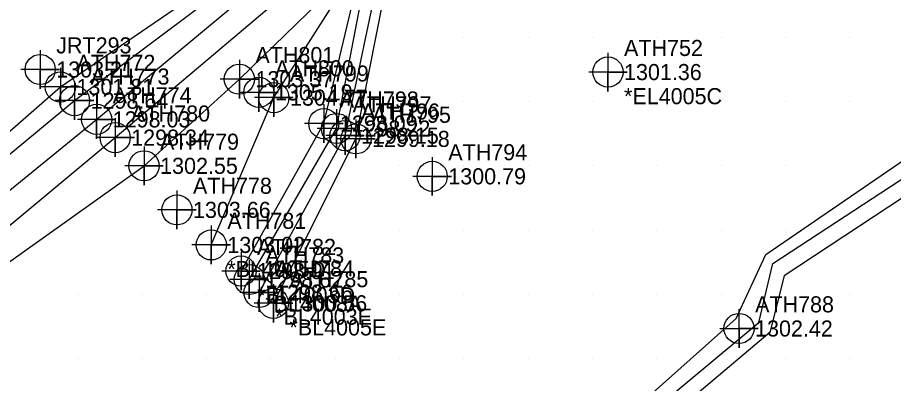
# Model space of a CAD drawing. Extents: x 1234484 to 1235382, y 695050 to 695510.
# Drawn here: x 1234800.6 to 1234936.8, y 695206.2 to 695263.1 of the extents above; entities that cross this region are included whole.
import ezdxf

# ---------------------------------------------------------------- set-up
doc = ezdxf.new("R2010")
doc.units = 0
for name, color, linetype in [('Exist DTM Breakline', 7, 'Continuous'), ('Exist DTM Breakline Cogo Comment', 7, 'Continuous'), ('Exist DTM Breakline Cogo Elevation', 7, 'Continuous'), ('Exist DTM Breakline Cogo Number', 7, 'Continuous'), ('Exist DTM Breakline Cogo Point CELL', 7, 'Continuous'), ('Exist DTM Breakline Underwater', 7, 'Continuous'), ('Exist DTM Drainline Cogo Comment', 7, 'Continuous'), ('Exist DTM Drainline Cogo Elevation', 7, 'Continuous'), ('Exist DTM Drainline Cogo Number', 7, 'Continuous'), ('Exist DTM Drainline Cogo Point CELL', 7, 'Continuous'), ('Exist DTM QL2 LIDAR Elevation Point', 7, 'Continuous'), ('Exist DTM Regular Point CELL', 7, 'Continuous'), ('Exist DTM Regular Point Cogo Elevation', 7, 'Continuous'), ('Exist DTM Regular Point Cogo Number', 7, 'Continuous'), ('Exist DTM Regular Point Underwater CELL', 7, 'Continuous'), ('Exist DTM Regular Point Underwater Cogo Comment', 7, 'Continuous'), ('Exist DTM Regular Point Underwater Cogo Elevation', 7, 'Continuous'), ('Exist DTM Regular Point Underwater Cogo Number', 7, 'Continuous'), ('Exist Hydro Stream or Body of Water', 7, 'Continuous'), ('Exist Hydro Stream or Body of Water Cogo Elevation', 7, 'Continuous'), ('Exist Hydro Stream or Body of Water Cogo Number', 7, 'Continuous'), ('Exist Hydro Stream or Body of Water Cogo Point CELL', 7, 'Continuous'), ('Old_Level_50', 7, 'Continuous')]:
    doc.layers.add(name, color=color, linetype=linetype)

msp = doc.modelspace()

# ---------------------------------------------------------------- linework, layer by layer
at = {"layer": 'Exist DTM Breakline'}
for points in [[(1234766.2, 695216.412), (1234807.252, 695252.276), (1234839.673, 695274.467), (1234869.326, 695284.86), (1234890.801, 695299.09), (1234911.196, 695302.79), (1234918.594, 695307.818)], [(1234933.683, 695295.436), (1234929.419, 695292.356), (1234942.895, 695281.98), (1234955.338, 695274.07), (1234960.662, 695260.925), (1234955.311, 695244.507), (1234951.042, 695246.761), (1234943.062, 695238.239), (1234919.786, 695222.886), (1234917.573, 695214.076), (1234899.933, 695199.243), (1234885.657, 695179.089)], [(1234882.128, 695182.331), (1234896.107, 695201.799), (1234912.336, 695216.249), (1234916.953, 695226.235), (1234940.483, 695242.348), (1234951.207, 695257.798), (1234946.446, 695265.278), (1234936.421, 695274.091), (1234919.314, 695287.826), (1234914.388, 695289.733)], [(1234840.371, 695218.638), (1234853.212, 695244.202), (1234858.487, 695270.963), (1234871.461, 695273.745), (1234897.697, 695279.312), (1234915.088, 695274.445), (1234918.81, 695282.981)], [(1234773.364, 695206.653), (1234820.257, 695240.015), (1234835.082, 695253.487), (1234852.804, 695270.766)], [(1234830.712, 695227.716), (1234840.448, 695250.618), (1234853.055, 695270.415)]]:
    msp.add_lwpolyline(points, dxfattribs=at)
at = {"layer": 'Exist DTM Breakline Cogo Point CELL'}
for points in [[(1234835.082, 695256.487), (1234835.082, 695250.487), (1234835.082, 695253.487), (1234838.082, 695253.487), (1234832.082, 695253.487)], [(1234807.252, 695255.276), (1234807.252, 695249.276), (1234807.252, 695252.276), (1234810.252, 695252.276), (1234804.252, 695252.276)], [(1234840.448, 695253.618), (1234840.448, 695247.618), (1234840.448, 695250.618), (1234843.448, 695250.618), (1234837.448, 695250.618)], [(1234853.212, 695247.202), (1234853.212, 695241.202), (1234853.212, 695244.202), (1234856.212, 695244.202), (1234850.212, 695244.202)], [(1234820.257, 695243.015), (1234820.257, 695237.015), (1234820.257, 695240.015), (1234823.257, 695240.015), (1234817.257, 695240.015)], [(1234830.712, 695230.716), (1234830.712, 695224.716), (1234830.712, 695227.716), (1234833.712, 695227.716), (1234827.712, 695227.716)], [(1234840.371, 695221.638), (1234840.371, 695215.638), (1234840.371, 695218.638), (1234843.371, 695218.638), (1234837.371, 695218.638)]]:
    msp.add_lwpolyline(points, dxfattribs=at)
for centre in [(1234835.082, 695253.487), (1234807.252, 695252.276), (1234840.448, 695250.618), (1234853.212, 695244.202), (1234820.257, 695240.015), (1234830.712, 695227.716), (1234840.371, 695218.638)]:
    msp.add_circle(centre, 2.344, dxfattribs=at)
at = {"layer": 'Exist DTM Breakline Underwater'}
msp.add_lwpolyline([(1234766.421, 695209.389), (1234812.885, 695247.237), (1234843.411, 695272.621), (1234869.986, 695279.055), (1234895.378, 695289.036), (1234916.238, 695295.408), (1234934.131, 695306.081), (1234961.466, 695329.617), (1234991.436, 695342.664), (1235009.265, 695346.147), (1235040.352, 695365.623), (1235072.367, 695380.008), (1235092.174, 695396.335)], dxfattribs=at)
at = {"layer": 'Exist DTM Drainline Cogo Point CELL'}
for points in [[(1234809.451, 695253.146), (1234809.451, 695247.146), (1234809.451, 695250.146), (1234812.451, 695250.146), (1234806.451, 695250.146)], [(1234848.212, 695249.579), (1234848.212, 695243.579), (1234848.212, 695246.579), (1234851.212, 695246.579), (1234845.212, 695246.579)], [(1234815.763, 695247.4), (1234815.763, 695241.4), (1234815.763, 695244.4), (1234818.763, 695244.4), (1234812.763, 695244.4)], [(1234851.51, 695247.706), (1234851.51, 695241.706), (1234851.51, 695244.706), (1234854.51, 695244.706), (1234848.51, 695244.706)], [(1234835.336, 695226.655), (1234835.336, 695220.655), (1234835.336, 695223.655), (1234838.336, 695223.655), (1234832.336, 695223.655)], [(1234838.142, 695223.308), (1234838.142, 695217.308), (1234838.142, 695220.308), (1234841.142, 695220.308), (1234835.142, 695220.308)]]:
    msp.add_lwpolyline(points, dxfattribs=at)
for centre in [(1234809.451, 695250.146), (1234848.212, 695246.579), (1234815.763, 695244.4), (1234851.51, 695244.706), (1234835.336, 695223.655), (1234838.142, 695220.308)]:
    msp.add_circle(centre, 2.344, dxfattribs=at)
at = {"layer": 'Exist DTM QL2 LIDAR Elevation Point'}
for p, q in [((1234870, 695260), (1234870, 695260)), ((1234880, 695260), (1234880, 695260)), ((1234890, 695260), (1234890, 695260)), ((1234900, 695260), (1234900, 695260)), ((1234910, 695260), (1234910, 695260)), ((1234920, 695260), (1234920, 695260)), ((1234930, 695260), (1234930, 695260)), ((1234860, 695250), (1234860, 695250)), ((1234870, 695250), (1234870, 695250)), ((1234880, 695250), (1234880, 695250)), ((1234890, 695250), (1234890, 695250)), ((1234900, 695250), (1234900, 695250)), ((1234910, 695250), (1234910, 695250)), ((1234920, 695250), (1234920, 695250)), ((1234930, 695250), (1234930, 695250)), ((1234860, 695240), (1234860, 695240)), ((1234870, 695240), (1234870, 695240)), ((1234880, 695240), (1234880, 695240)), ((1234890, 695240), (1234890, 695240)), ((1234900, 695240), (1234900, 695240)), ((1234910, 695240), (1234910, 695240)), ((1234920, 695240), (1234920, 695240)), ((1234860, 695230), (1234860, 695230)), ((1234870, 695230), (1234870, 695230)), ((1234880, 695230), (1234880, 695230)), ((1234890, 695230), (1234890, 695230)), ((1234900, 695230), (1234900, 695230)), ((1234910, 695230), (1234910, 695230)), ((1234920, 695230), (1234920, 695230)), ((1234810, 695220), (1234810, 695220)), ((1234820, 695220), (1234820, 695220)), ((1234830, 695220), (1234830, 695220)), ((1234850, 695220), (1234850, 695220)), ((1234860, 695220), (1234860, 695220)), ((1234870, 695220), (1234870, 695220)), ((1234880, 695220), (1234880, 695220)), ((1234890, 695220), (1234890, 695220)), ((1234900, 695220), (1234900, 695220)), ((1234910, 695220), (1234910, 695220)), ((1234930, 695220), (1234930, 695220)), ((1234810, 695210), (1234810, 695210)), ((1234820, 695210), (1234820, 695210)), ((1234830, 695210), (1234830, 695210)), ((1234840, 695210), (1234840, 695210)), ((1234850, 695210), (1234850, 695210)), ((1234860, 695210), (1234860, 695210)), ((1234870, 695210), (1234870, 695210)), ((1234880, 695210), (1234880, 695210)), ((1234890, 695210), (1234890, 695210)), ((1234900, 695210), (1234900, 695210)), ((1234920, 695210), (1234920, 695210)), ((1234930, 695210), (1234930, 695210))]:
    msp.add_line(p, q, dxfattribs=at)
at = {"layer": 'Exist DTM Regular Point CELL'}
for points in [[(1234804.106, 695257.991), (1234804.106, 695251.991), (1234804.106, 695254.991), (1234807.106, 695254.991), (1234801.106, 695254.991)], [(1234892.402, 695257.594), (1234892.402, 695251.594), (1234892.402, 695254.594), (1234895.402, 695254.594), (1234889.402, 695254.594)], [(1234838.116, 695254.431), (1234838.116, 695248.431), (1234838.116, 695251.431), (1234841.116, 695251.431), (1234835.116, 695251.431)], [(1234865.072, 695241.38), (1234865.072, 695235.38), (1234865.072, 695238.38), (1234868.072, 695238.38), (1234862.072, 695238.38)], [(1234825.371, 695236.162), (1234825.371, 695230.162), (1234825.371, 695233.162), (1234828.371, 695233.162), (1234822.371, 695233.162)]]:
    msp.add_lwpolyline(points, dxfattribs=at)
for centre in [(1234804.106, 695254.991), (1234892.402, 695254.594), (1234838.116, 695251.431), (1234865.072, 695238.38), (1234825.371, 695233.162)]:
    msp.add_circle(centre, 2.344, dxfattribs=at)
at = {"layer": 'Exist DTM Regular Point Underwater CELL'}
for points in [[(1234812.885, 695250.237), (1234812.885, 695244.237), (1234812.885, 695247.237), (1234815.885, 695247.237), (1234809.885, 695247.237)], [(1234850.191, 695248.82), (1234850.191, 695242.82), (1234850.191, 695245.82), (1234853.191, 695245.82), (1234847.191, 695245.82)], [(1234836.619, 695225.333), (1234836.619, 695219.333), (1234836.619, 695222.333), (1234839.619, 695222.333), (1234833.619, 695222.333)]]:
    msp.add_lwpolyline(points, dxfattribs=at)
for centre in [(1234812.885, 695247.237), (1234850.191, 695245.82), (1234836.619, 695222.333)]:
    msp.add_circle(centre, 2.344, dxfattribs=at)
at = {"layer": 'Exist Hydro Stream or Body of Water'}
for points in [[(1234766.439, 695214.543), (1234809.451, 695250.146), (1234840.783, 695273.683), (1234870.231, 695281.467), (1234894.384, 695292.767), (1234915.014, 695298.345), (1234929.933, 695306.511), (1234953.845, 695329.807), (1234986.204, 695341.472), (1235008.526, 695348.915), (1235037.336, 695368.653), (1235069.491, 695383.302), (1235088.448, 695400.861)], [(1234770.872, 695207.044), (1234815.763, 695244.4), (1234847.025, 695270.849), (1234870.723, 695276.867), (1234895.944, 695286.356), (1234916.555, 695293.487), (1234933.154, 695302.663)], [(1234884.024, 695180.655), (1234897.944, 695200.742), (1234915.887, 695215.628), (1234918.027, 695224.801), (1234941.893, 695240.452), (1234957.27, 695259.086), (1234951.207, 695270.685), (1234942.31, 695277.234), (1234922.587, 695292.008)], [(1234838.142, 695220.308), (1234851.51, 695244.706), (1234857.192, 695271.621)], [(1234835.336, 695223.655), (1234848.212, 695246.579), (1234854.006, 695270.943)]]:
    msp.add_lwpolyline(points, dxfattribs=at)
at = {"layer": 'Exist Hydro Stream or Body of Water Cogo Point CELL'}
msp.add_lwpolyline([(1234909.779, 695214.725), (1234915.779, 695214.725), (1234912.779, 695214.725), (1234912.779, 695211.725), (1234912.779, 695217.725)], dxfattribs=at)
msp.add_circle((1234912.779, 695214.725), 2.344, dxfattribs=at)
at = {"layer": 'Old_Level_50'}
msp.add_lwpolyline([(1234836.619, 695222.333), (1234850.191, 695245.82), (1234855.246, 695272.274)], dxfattribs=at)

# ---------------------------------------------------------------- texts
at = {"layer": 'Exist DTM Breakline Cogo Comment'}
for s, p in [('*EL4005C', (1234894.902, 695249.594)), ('*BL4005D', (1234833.212, 695222.716)), ('*BL4005E', (1234842.871, 695213.638))]:
    msp.add_text(s, height=2.5, dxfattribs=at).set_placement(p)
at = {"layer": 'Exist DTM Breakline Cogo Elevation'}
for s, p in [('1303.37', (1234837.582, 695252.237)), ('1301.36', (1234894.902, 695253.344)), ('1301.81', (1234809.752, 695251.026)), ('1304.77', (1234842.948, 695249.368)), ('1299.18', (1234855.712, 695242.952)), ('1302.55', (1234822.757, 695238.765)), ('1303.02', (1234833.212, 695226.466)), ('1300.56', (1234842.871, 695217.388))]:
    msp.add_text(s, height=2.5, dxfattribs=at).set_placement(p)
at = {"layer": 'Exist DTM Breakline Cogo Number'}
for s, p in [('ATH752', (1234894.902, 695257.094)), ('ATH801', (1234837.582, 695255.987)), ('ATH772', (1234809.752, 695254.776)), ('ATH799', (1234842.948, 695253.118)), ('ATH795', (1234855.712, 695246.702)), ('ATH779', (1234822.757, 695242.515)), ('ATH781', (1234833.212, 695230.216)), ('ATH785', (1234842.871, 695221.138))]:
    msp.add_text(s, height=2.5, dxfattribs=at).set_placement(p)
at = {"layer": 'Exist DTM Drainline Cogo Comment'}
for s, p in [('*BL4003D', (1234837.836, 695218.655)), ('*BL4003E', (1234840.642, 695215.308))]:
    msp.add_text(s, height=2.5, dxfattribs=at).set_placement(p)
at = {"layer": 'Exist DTM Drainline Cogo Elevation'}
for s, p in [('1298.64', (1234811.951, 695248.896)), ('1298.09', (1234850.712, 695245.329)), ('1298.34', (1234818.263, 695243.15)), ('1298.15', (1234854.01, 695243.456)), ('1298.91', (1234837.836, 695222.405)), ('1298.66', (1234840.642, 695219.058))]:
    msp.add_text(s, height=2.5, dxfattribs=at).set_placement(p)
at = {"layer": 'Exist DTM Drainline Cogo Number'}
for s, p in [('ATH773', (1234811.951, 695252.646)), ('ATH798', (1234850.712, 695249.079)), ('ATH780', (1234818.263, 695246.9)), ('ATH796', (1234854.01, 695247.206)), ('ATH782', (1234837.836, 695226.155)), ('ATH784', (1234840.642, 695222.808))]:
    msp.add_text(s, height=2.5, dxfattribs=at).set_placement(p)
at = {"layer": 'Exist DTM Regular Point Cogo Elevation'}
for s, p in [('1303.21', (1234806.606, 695253.741)), ('1305.19', (1234840.616, 695250.181)), ('1300.79', (1234867.572, 695237.13)), ('1303.66', (1234827.871, 695231.912))]:
    msp.add_text(s, height=2.5, dxfattribs=at).set_placement(p)
at = {"layer": 'Exist DTM Regular Point Cogo Number'}
for s, p in [('JRT293', (1234806.606, 695257.491)), ('ATH800', (1234840.616, 695253.931)), ('ATH794', (1234867.572, 695240.88)), ('ATH778', (1234827.871, 695235.662))]:
    msp.add_text(s, height=2.5, dxfattribs=at).set_placement(p)
at = {"layer": 'Exist DTM Regular Point Underwater Cogo Comment'}
msp.add_text('*BL4008A', height=2.5, dxfattribs=at).set_placement((1234839.119, 695217.333))
at = {"layer": 'Exist DTM Regular Point Underwater Cogo Elevation'}
for s, p in [('1298.03', (1234815.385, 695245.987)), ('1298.22', (1234852.691, 695244.57)), ('1298.62', (1234839.119, 695221.083))]:
    msp.add_text(s, height=2.5, dxfattribs=at).set_placement(p)
at = {"layer": 'Exist DTM Regular Point Underwater Cogo Number'}
for s, p in [('ATH774', (1234815.385, 695249.737)), ('ATH797', (1234852.691, 695248.32)), ('ATH783', (1234839.119, 695224.833))]:
    msp.add_text(s, height=2.5, dxfattribs=at).set_placement(p)
at = {"layer": 'Exist Hydro Stream or Body of Water Cogo Elevation'}
msp.add_text('1302.42', height=2.5, dxfattribs=at).set_placement((1234915.279, 695213.475))
at = {"layer": 'Exist Hydro Stream or Body of Water Cogo Number'}
msp.add_text('ATH788', height=2.5, dxfattribs=at).set_placement((1234915.279, 695217.225))

doc.saveas('drawing.dxf')
